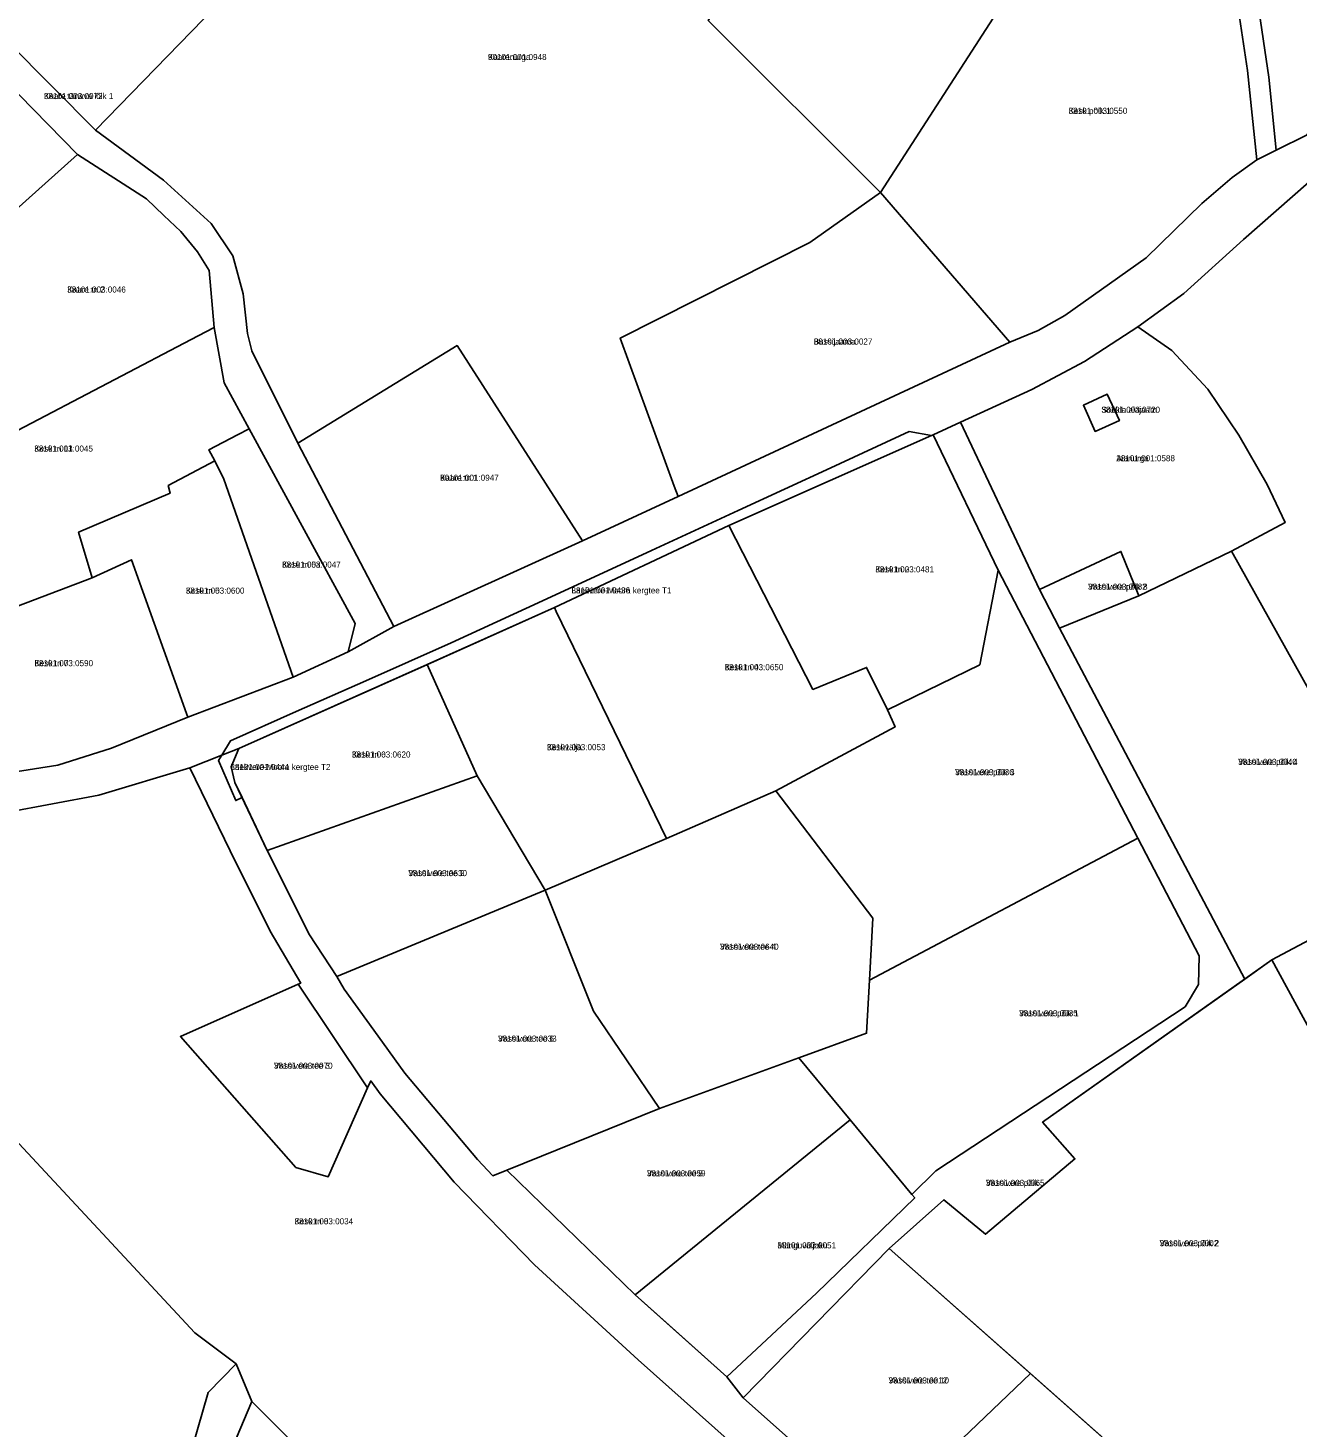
# Model space of a CAD drawing. Extents: x 630783 to 668840, y 6537056 to 6585920.
# Drawn here: x 646847.6 to 647161.9, y 6550283.5 to 6550629.9 of the extents above; entities that cross this region are included whole.
import ezdxf

# ---------------------------------------------------------------- set-up
doc = ezdxf.new("R2010")
doc.units = 0
for name, color, linetype in [('L_AADRESS', 7, 'Continuous'), ('PIIR', 7, 'Continuous'), ('TUNNUS', 7, 'Continuous')]:
    doc.layers.add(name, color=color, linetype=linetype)

msp = doc.modelspace()

# ---------------------------------------------------------------- linework, layer by layer
at = {"layer": 'PIIR'}
for points in [[(646709.32, 6550810.4), (646704, 6550821.69), (646492.61, 6551260.32), (646286.93, 6551684.82), (646280.87, 6551696.69), (646276.89, 6551704.42), (646407.05, 6551771.23), (646414.9, 6551763.3), (646697.48, 6551423.51), (646979.51, 6551083.84), (647162.02, 6551170.57), (647372.53, 6550902.89), (647353.67, 6550854.07), (647324.52, 6550778.06), (647244.38, 6550805.98), (647164.18, 6550603.46), (647156.44, 6550599.71), (647154.63, 6550617.75), (647151.93, 6550636.17), (647147.53, 6550641.39), (647140.39, 6550646.56), (647067.31, 6550681.38), (647003.91, 6550800.32), (646924.22, 6550896.32)], [(646774.22, 6550697.65), (646773.2, 6550700.65), (646771.47, 6550705.55), (646755.04, 6550726.91), (646746.36, 6550725.6), (646709.32, 6550810.4), (646924.22, 6550896.32), (647003.91, 6550800.32), (647067.31, 6550681.38), (647064.65, 6550677.66), (647103.39, 6550658.69), (647102.85, 6550657.86), (647058.57, 6550589.2), (647015.95, 6550631.76), (647030.54, 6550654.11), (646995.03, 6550739.11), (646978.91, 6550783.83), (646799.61, 6550669.91)], [(646978.91, 6550783.83), (646995.03, 6550739.11), (646864.36, 6550604.65), (646799.61, 6550669.91)], [(646881.14, 6550592.23), (646864.36, 6550604.65), (646995.03, 6550739.11), (647030.54, 6550654.11), (647015.95, 6550631.76), (647058.57, 6550589.2), (647041.13, 6550576.83), (646994.2, 6550553.19), (647007.55, 6550516.54), (647008.49, 6550513.96), (646984.83, 6550502.99), (646953.83, 6550551.31), (646914.41, 6550527.22), (646903.05, 6550550.04), (646901.94, 6550554.31), (646900.87, 6550564.14), (646898.31, 6550573.57), (646892.98, 6550581.51)], [(647064.65, 6550677.66), (647067.31, 6550681.38), (647140.39, 6550646.56), (647147.53, 6550641.39), (647151.93, 6550636.17), (647154.63, 6550617.75), (647156.44, 6550599.71), (647151.7, 6550597.31), (647149.4, 6550619.41), (647147.44, 6550632.6), (647146.75, 6550634.28), (647144.06, 6550637), (647138.23, 6550641.85), (647134.37, 6550644.31), (647103.39, 6550658.69)], [(646751.67, 6550604.56), (646746.19, 6550599.92), (646743.37, 6550607.55), (646794.75, 6550665.26), (646859.93, 6550598.59), (646821.44, 6550564.18), (646792.85, 6550538.67), (646777.78, 6550558.49), (646783.86, 6550564.62), (646764.64, 6550592.6)], [(647103.39, 6550658.69), (647134.37, 6550644.31), (647138.23, 6550641.85), (647144.06, 6550637), (647146.75, 6550634.28), (647147.44, 6550632.6), (647149.4, 6550619.41), (647151.7, 6550597.31), (647145.55, 6550592.92), (647138.11, 6550586.46), (647124.31, 6550573.08), (647104.21, 6550558.8), (647097.55, 6550555.04), (647090.58, 6550552.15), (647058.57, 6550589.2), (647102.85, 6550657.86)], [(647145.42, 6550500.44), (647158.74, 6550507.56), (647154.22, 6550516.96), (647147.23, 6550529.15), (647139.57, 6550540.55), (647130.67, 6550550.09), (647122.27, 6550555.96), (647133.6, 6550564.23), (647148.42, 6550577.58), (647164.58, 6550591.74), (647175.17, 6550598.58), (647186.87, 6550603.73), (647201.19, 6550607.62), (647211.05, 6550607.69), (647231.12, 6550601.76), (647240.71, 6550598.74), (647257.88, 6550591.82), (647317.81, 6550568.94), (647286.96, 6550412.77), (647224.14, 6550454.68), (647187.76, 6550424.63)], [(646859.93, 6550598.59), (646876.93, 6550587.66), (646881.26, 6550583.54), (646885.49, 6550579.57), (646889.61, 6550574.51), (646892.51, 6550569.89), (646893.69, 6550555.83), (646889.77, 6550553.78), (646845.05, 6550530.3), (646834.46, 6550549.84), (646821.44, 6550564.18)], [(646994.2, 6550553.19), (647041.13, 6550576.83), (647058.57, 6550589.2), (647090.58, 6550552.15), (647008.49, 6550513.96), (647007.55, 6550516.54)], [(646821.44, 6550564.18), (646834.46, 6550549.84), (646845.05, 6550530.3), (646889.77, 6550553.78), (646893.69, 6550555.83), (646896.15, 6550542.08), (646902.35, 6550530.74), (646899.5, 6550529.25), (646892.42, 6550525.56), (646893.87, 6550522.83), (646882.35, 6550516.74), (646882.84, 6550514.81), (646860.18, 6550505.15), (646863.56, 6550493.82), (646842.92, 6550486.02), (646792.85, 6550538.67)], [(647078.36, 6550532.36), (647095.99, 6550540.43), (647109.09, 6550547.38), (647122.27, 6550555.96), (647130.67, 6550550.09), (647139.57, 6550540.55), (647147.23, 6550529.15), (647154.22, 6550516.96), (647158.74, 6550507.56), (647145.42, 6550500.44), (647122.52, 6550489.43), (647118.06, 6550500.4), (647097.95, 6550490.96)], [(646938.2, 6550481.84), (646914.41, 6550527.22), (646953.83, 6550551.31), (646984.83, 6550502.99)], [(647111.69, 6550530.09), (647108.77, 6550536.58), (647114.67, 6550539.3), (647117.7, 6550532.76)], [(647108.77, 6550536.58), (647111.69, 6550530.09), (647117.7, 6550532.76), (647114.67, 6550539.3)], [(647071.58, 6550529.24), (647078.36, 6550532.36), (647097.95, 6550490.96), (647102.9, 6550481.44), (647148.73, 6550394.56), (647098.69, 6550359.17), (647106.68, 6550350.1), (647084.57, 6550331.46), (647074.27, 6550339.99), (647060.76, 6550327.93), (647024.58, 6550290.97), (647020.57, 6550296.18), (647042.78, 6550316.87), (647067.04, 6550340.42), (647066.32, 6550341.29), (647072.26, 6550347.13), (647133.93, 6550387.72), (647137.24, 6550393.24), (647137.43, 6550400.37), (647122.26, 6550429.48), (647087.72, 6550495.72)], [(646902.35, 6550530.74), (646928.61, 6550482.6), (646926.87, 6550475.58), (646913.22, 6550469.25), (646896.13, 6550518.31), (646893.87, 6550522.83), (646892.42, 6550525.56), (646899.5, 6550529.25)], [(646946.46, 6550472.38), (646899.79, 6550451.6), (646895.58, 6550449.97), (646897.74, 6550453.52), (646913.97, 6550460.76), (646931.24, 6550468.36), (646952.37, 6550477.75), (646974.95, 6550488.19), (647001.9, 6550500.64), (647023.38, 6550510.56), (647046.26, 6550521.08), (647065.69, 6550530.06), (647071.18, 6550529.07), (647021.05, 6550506.84), (646977.89, 6550486.5)], [(647087.72, 6550495.72), (647083.15, 6550472.34), (647060.29, 6550461.19), (647055.12, 6550471.7), (647041.85, 6550466.25), (647021.05, 6550506.84), (647071.18, 6550529.07), (647071.58, 6550529.24)], [(646863.56, 6550493.82), (646860.18, 6550505.15), (646882.84, 6550514.81), (646882.35, 6550516.74), (646893.87, 6550522.83), (646896.13, 6550518.31), (646913.22, 6550469.25), (646887.22, 6550459.42), (646886.89, 6550460.33), (646873.28, 6550498.33)], [(647041.85, 6550466.25), (647055.12, 6550471.7), (647060.29, 6550461.19), (647062.19, 6550456.96), (647032.65, 6550441.12), (647005.62, 6550429.37), (646978.34, 6550485.57), (646977.89, 6550486.5), (647021.05, 6550506.84)], [(647118.06, 6550500.4), (647122.52, 6550489.43), (647102.9, 6550481.44), (647097.95, 6550490.96)], [(647102.9, 6550481.44), (647122.52, 6550489.43), (647145.42, 6550500.44), (647187.76, 6550424.63), (647191.26, 6550418.36), (647155.44, 6550399.31), (647148.73, 6550394.56)], [(646828.12, 6550480.62), (646842.92, 6550486.02), (646863.56, 6550493.82), (646873.28, 6550498.33), (646886.89, 6550460.33), (646887.22, 6550459.42), (646868.31, 6550451.71), (646855.04, 6550447.47), (646843.45, 6550445.68), (646839.58, 6550445.72), (646834.62, 6550446.04), (646830.19, 6550446.97), (646821.1, 6550450.03), (646796.8, 6550458.73)], [(647032.65, 6550441.12), (647062.19, 6550456.96), (647060.29, 6550461.19), (647083.15, 6550472.34), (647087.72, 6550495.72), (647122.26, 6550429.48), (647055.86, 6550394.33), (647056.7, 6550409.67)], [(646946.45, 6550472.41), (646977.89, 6550486.5), (646978.34, 6550485.57), (647005.62, 6550429.37), (646975.6, 6550416.56), (646958.76, 6550444.86)], [(646898.8, 6550443.25), (646897.9, 6550447.13), (646899.79, 6550451.63), (646946.45, 6550472.41), (646958.76, 6550444.86), (646906.84, 6550426.38)], [(646895.58, 6550449.97), (646899.79, 6550451.6), (646897.9, 6550447.13), (646898.8, 6550443.25), (646900.67, 6550439.48), (646899.05, 6550438.73), (646894.79, 6550448.68)], [(647187.76, 6550424.63), (647224.14, 6550454.68), (647286.96, 6550412.77), (647246.17, 6550206.28), (647236.62, 6550163.55), (647189.43, 6550196.4), (647152.7, 6550167.93), (647138.9, 6550181.43), (647102.69, 6550219.31), (647140.09, 6550257.65), (647203.91, 6550310.11), (647155.44, 6550399.31), (647191.26, 6550418.36)], [(646924.04, 6550395.25), (646917.27, 6550405.49), (646906.84, 6550426.38), (646958.76, 6550444.86), (646975.6, 6550416.56)], [(646987.53, 6550386.6), (646975.6, 6550416.56), (647005.62, 6550429.37), (647032.65, 6550441.12), (647056.7, 6550409.67), (647055.86, 6550394.33), (647055.14, 6550381.18), (647038.34, 6550375.07), (647003.86, 6550362.56)], [(647055.14, 6550381.18), (647055.86, 6550394.33), (647122.26, 6550429.48), (647137.43, 6550400.37), (647137.24, 6550393.24), (647133.93, 6550387.72), (647072.26, 6550347.13), (647066.32, 6550341.29), (647051.06, 6550359.71), (647038.34, 6550375.07)], [(646924.04, 6550395.25), (646975.6, 6550416.56), (646987.53, 6550386.6), (647003.86, 6550362.56), (646966.1, 6550347.31), (646962.64, 6550345.92), (646958.85, 6550349.97), (646940.9, 6550371.3), (646934.28, 6550380.49), (646925.89, 6550392.1)], [(647155.44, 6550399.31), (647203.91, 6550310.11), (647140.09, 6550257.65), (647060.76, 6550327.93), (647074.27, 6550339.99), (647084.57, 6550331.46), (647106.68, 6550350.1), (647098.69, 6550359.17)], [(646931.68, 6550367.66), (646921.93, 6550345.66), (646913.95, 6550347.96), (646885.34, 6550380.36), (646914.47, 6550393.3)], [(646966.1, 6550347.31), (647003.86, 6550362.56), (647038.34, 6550375.07), (647051.06, 6550359.71), (646997.84, 6550316.46)], [(646997.84, 6550316.46), (647051.06, 6550359.71), (647066.32, 6550341.29), (647067.04, 6550340.42), (647042.78, 6550316.87), (647020.57, 6550296.18), (647006.28, 6550308.92)], [(646821.1, 6550351.81), (646825, 6550353.65), (646842.12, 6550357.33), (646888.92, 6550307.07), (646899.17, 6550299.36), (646892.2, 6550292.32), (646886.92, 6550273.94), (646883.27, 6550267.04), (646868.69, 6550247.75), (646856.56, 6550232.19), (646845.35, 6550227.58), (646813.76, 6550214.73), (646793.16, 6550206.63), (646789.64, 6550208.14), (646770.09, 6550277.6), (646762.9, 6550292.51), (646804.46, 6550308.2), (646807.52, 6550310.88), (646810.91, 6550323.02), (646811.82, 6550336.45), (646816.89, 6550343.77)], [(647060.76, 6550327.93), (647095.68, 6550296.99), (647058.2, 6550261.1), (647024.58, 6550290.97)], [(646899.17, 6550299.36), (646903.03, 6550290.02), (646889.79, 6550258.86), (646876.19, 6550236.85), (646869.96, 6550229.74), (646851.52, 6550220.86), (646824.23, 6550207.8), (646793.5, 6550194.02), (646789.64, 6550208.14), (646793.16, 6550206.63), (646813.76, 6550214.73), (646845.35, 6550227.58), (646856.56, 6550232.19), (646868.69, 6550247.75), (646883.27, 6550267.04), (646886.92, 6550273.94), (646892.2, 6550292.32)], [(647058.2, 6550261.1), (647095.68, 6550296.99), (647140.09, 6550257.65), (647102.69, 6550219.31), (647085.52, 6550235.95)], [(646910.66, 6550242.53), (646889.79, 6550258.86), (646903.03, 6550290.02), (646941.52, 6550251.35), (646969.83, 6550220.91), (646960.01, 6550202.74), (646975.32, 6550185.79), (646967.84, 6550180.61), (646911.18, 6550243.16)]]:
    msp.add_lwpolyline(points, close=True, dxfattribs=at)
for points in [[(646799.61, 6550669.91), (646864.36, 6550604.65), (646881.14, 6550592.23), (646892.98, 6550581.51), (646898.31, 6550573.57), (646900.87, 6550564.14), (646901.94, 6550554.31), (646903.05, 6550550.04), (646914.41, 6550527.22), (646938.2, 6550481.84), (646926.87, 6550475.58), (646928.61, 6550482.6), (646902.35, 6550530.74), (646896.15, 6550542.08), (646893.69, 6550555.83), (646892.51, 6550569.89), (646889.61, 6550574.51), (646885.49, 6550579.57), (646881.26, 6550583.54), (646876.93, 6550587.66), (646859.93, 6550598.59), (646794.75, 6550665.26)], [(646843.45, 6550445.68), (646855.04, 6550447.47), (646868.31, 6550451.71), (646887.22, 6550459.42), (646913.22, 6550469.25), (646926.87, 6550475.58), (646938.2, 6550481.84), (646984.83, 6550502.99), (647008.49, 6550513.96), (647090.58, 6550552.15), (647097.55, 6550555.04), (647104.21, 6550558.8), (647124.31, 6550573.08), (647138.11, 6550586.46), (647145.55, 6550592.92), (647151.7, 6550597.31), (647156.44, 6550599.71), (647164.18, 6550603.46)], [(647164.58, 6550591.74), (647148.42, 6550577.58), (647133.6, 6550564.23), (647122.27, 6550555.96), (647109.09, 6550547.38), (647095.99, 6550540.43), (647078.36, 6550532.36), (647071.58, 6550529.24), (647071.18, 6550529.07), (647065.69, 6550530.06), (647046.26, 6550521.08), (647023.38, 6550510.56), (647001.9, 6550500.64), (646974.95, 6550488.19), (646952.37, 6550477.75), (646931.24, 6550468.36), (646913.97, 6550460.76), (646897.74, 6550453.52), (646895.58, 6550449.97), (646887.71, 6550446.88), (646865.18, 6550440.12), (646842.26, 6550435.81)], [(647028.97, 6550273.28), (646998.62, 6550300.33), (646972.98, 6550323.88), (646953.09, 6550344.36), (646934.78, 6550366.15), (646932.44, 6550369.38), (646931.68, 6550367.66), (646914.47, 6550393.3), (646915.13, 6550393.6), (646907.58, 6550406.45), (646897.63, 6550426.34), (646887.71, 6550446.88), (646895.58, 6550449.97), (646894.79, 6550448.68), (646899.05, 6550438.73), (646900.67, 6550439.48), (646906.84, 6550426.38), (646917.27, 6550405.49), (646924.04, 6550395.25), (646925.89, 6550392.1), (646934.28, 6550380.49), (646940.9, 6550371.3), (646958.85, 6550349.97), (646962.64, 6550345.92), (646966.1, 6550347.31), (646997.84, 6550316.46), (647020.57, 6550296.18), (647024.58, 6550290.97), (647058.2, 6550261.1)], [(646842.26, 6550435.81), (646865.18, 6550440.12), (646887.71, 6550446.88), (646897.63, 6550426.34), (646907.58, 6550406.45), (646915.13, 6550393.6), (646914.47, 6550393.3), (646885.34, 6550380.36), (646913.95, 6550347.96), (646921.93, 6550345.66), (646931.68, 6550367.66), (646932.44, 6550369.38), (646934.78, 6550366.15), (646953.09, 6550344.36), (646972.98, 6550323.88), (646998.62, 6550300.33), (647028.97, 6550273.28)], [(646941.52, 6550251.35), (646903.03, 6550290.02), (646899.17, 6550299.36), (646888.92, 6550307.07), (646842.12, 6550357.33)]]:
    msp.add_lwpolyline(points, dxfattribs=at)

# ---------------------------------------------------------------- texts
at = {"layer": 'L_AADRESS'}
for s, p in [('Kaarenurga', (646961.46, 6550621.99)), ('Kaare tänava lõik 1', (646851.59, 6550612.32)), ('Kesk põik 1', (647105.14, 6550608.67)), ('Kaare tn 2', (646857.35, 6550564.45)), ('Bussijaama', (647042.07, 6550551.58)), ('Söökla alajaam', (647113.24, 6550534.71)), ('Kesk tn 11', (646849.21, 6550525.1)), ('Aianurga', (647116.93, 6550522.7)), ('Kaare tn 1', (646949.62, 6550517.88)), ('Kesk tn 5a', (646910.52, 6550496.39)), ('Kesk tn 2', (647057.31, 6550495.21)), ('Kesk tn 5', (646886.7, 6550489.95)), ('Laekvere-Moora kergtee T1', (646982.12, 6550490.01)), ('Vassivere põik 8', (647109.94, 6550490.92)), ('Kesk tn 7', (646849.25, 6550472)), ('Kesk tn 4', (647020.04, 6550471)), ('Keskvälja', (646976.04, 6550451.21)), ('Kesk tn 6', (646927.79, 6550449.4)), ('Vassivere põik 4', (647147.08, 6550447.58)), ('Laekvere-Moora kergtee T2', (646897.73, 6550446.31)), ('Vassivere põik 3', (647077.04, 6550445.02)), ('Vassivere tee 2', (646941.76, 6550420.05)), ('Vassivere tee 4', (647018.87, 6550401.84)), ('Vassivere põik 1', (647092.88, 6550385.38)), ('Vassivere tee 6', (646963.95, 6550379.1)), ('Vassivere tee 3', (646908.51, 6550372.39)), ('Vassivere tee 8', (647000.79, 6550345.77)), ('Vassivere põik', (647084.65, 6550343.41)), ('Kesk tn 8', (646913.6, 6550333.9)), ('Mänguväljaku', (647033.08, 6550327.95)), ('Vassivere põik 2', (647127.65, 6550328.48)), ('Vassivere tee 10', (647060.57, 6550294.52))]:
    msp.add_text(s, height=1.5, dxfattribs=at).set_placement(p)
at = {"layer": 'TUNNUS'}
for s, p in [('90101:001:0948', (646961.46, 6550621.99)), ('38101:003:0072', (646851.59, 6550612.32)), ('38101:003:0550', (647105.14, 6550608.67)), ('38101:003:0046', (646857.35, 6550564.45)), ('38101:003:0027', (647042.07, 6550551.58)), ('38101:003:0720', (647113.24, 6550534.71)), ('38101:003:0045', (646849.21, 6550525.1)), ('38101:001:0588', (647116.93, 6550522.7)), ('90101:001:0947', (646949.62, 6550517.88)), ('38101:003:0047', (646910.52, 6550496.39)), ('38101:003:0481', (647057.31, 6550495.21)), ('38101:003:0600', (646886.7, 6550489.95)), ('38101:001:0436', (646982.12, 6550490.01)), ('38101:003:0482', (647109.94, 6550490.92)), ('38101:003:0590', (646849.25, 6550472)), ('38101:003:0650', (647020.04, 6550471)), ('38101:003:0053', (646976.04, 6550451.21)), ('38101:003:0620', (646927.79, 6550449.4)), ('38101:003:0040', (647147.08, 6550447.58)), ('38101:001:0444', (646897.73, 6550446.31)), ('38101:003:0036', (647077.04, 6550445.02)), ('38101:003:0630', (646941.76, 6550420.05)), ('38101:003:0640', (647018.87, 6550401.84)), ('38101:003:0035', (647092.88, 6550385.38)), ('38101:003:0033', (646963.95, 6550379.1)), ('38101:003:0070', (646908.51, 6550372.39)), ('38101:003:0059', (647000.79, 6550345.77)), ('38101:003:0065', (647084.65, 6550343.41)), ('38101:003:0034', (646913.6, 6550333.9)), ('38101:003:0051', (647033.08, 6550327.95)), ('38101:003:0002', (647127.65, 6550328.48)), ('38101:003:0012', (647060.57, 6550294.52))]:
    msp.add_text(s, height=1.5, dxfattribs=at).set_placement(p)

doc.saveas('drawing.dxf')
